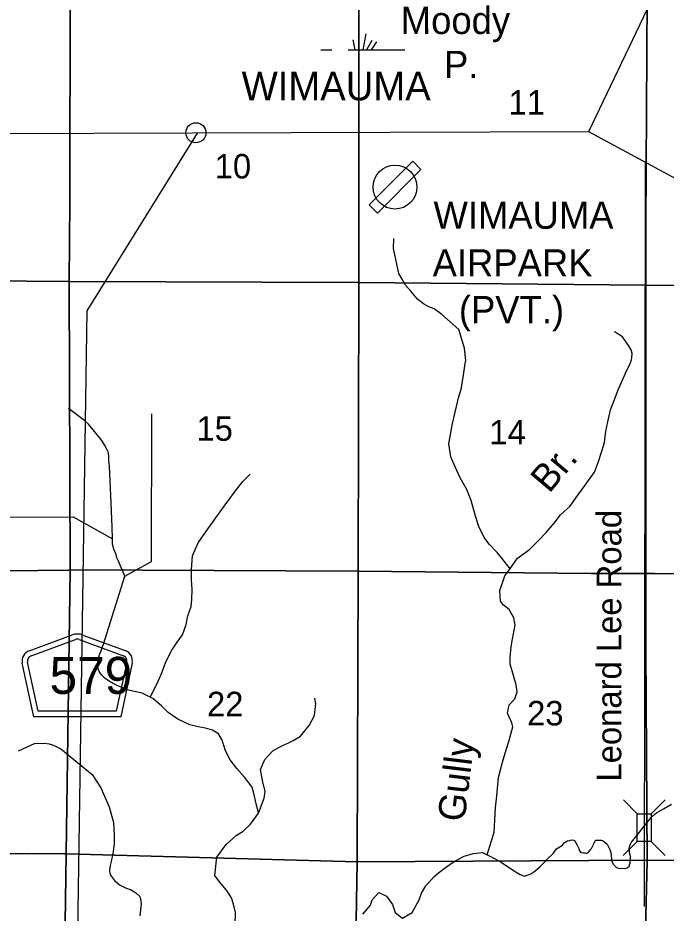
# Model space of a CAD drawing. Extents: x 380424 to 701066, y 1117407 to 1412949.
# Drawn here: x 557408 to 569307, y 1214030 to 1230461 of the extents above; entities that cross this region are included whole.
import ezdxf

# ---------------------------------------------------------------- set-up
doc = ezdxf.new("R2010")
doc.units = 0
for name, color, linetype in [('Airport Names', 7, 'Continuous'), ('Airports Landing Strip or Private Airport', 7, 'Continuous'), ('Bridges', 7, 'Continuous'), ('Bridges and Drawbridges Local Roads', 7, 'Continuous'), ('Communities Names with Post Office', 7, 'Continuous'), ('County Routes Highway Center Lines', 7, 'Continuous'), ('Local Roads Paved', 7, 'Continuous'), ('Local Roads Related Text', 7, 'Continuous'), ('Narrow Canals', 7, 'Continuous'), ('Narrow River Creek and Branch and Slough', 7, 'Continuous'), ('Narrow River Creek and Branch and Slough Text', 7, 'Continuous'), ('Roadshields County Roads', 7, 'Continuous'), ('Section Lines', 7, 'Continuous'), ('Section Numbers', 7, 'Continuous'), ('State Routes Highway Center Lines', 7, 'Continuous'), ('Swamps', 7, 'Continuous'), ('Town Centers', 7, 'Continuous')]:
    doc.layers.add(name, color=color, linetype=linetype)

msp = doc.modelspace()

# ---------------------------------------------------------------- linework, layer by layer
at = {"layer": 'Airports Landing Strip or Private Airport'}
msp.add_lwpolyline([(564655, 1227830), (563855, 1227030), (564006, 1226878), (564805, 1227680)], close=True, dxfattribs=at)
msp.add_circle((564330, 1227355), 403, dxfattribs=at)
at = {"layer": 'Bridges'}
msp.add_line((569033, 1215853), (569290, 1216109), dxfattribs=at)
at = {"layer": 'Bridges and Drawbridges Local Roads'}
for p, q in [((568777, 1215854), (568522, 1216110)), ((568776, 1215342), (568520, 1215086)), ((569032, 1215341), (569288, 1215085))]:
    msp.add_line(p, q, dxfattribs=at)
msp.add_lwpolyline([(569033, 1215853), (569032, 1215341), (568776, 1215342), (568777, 1215854)], close=True, dxfattribs=at)
at = {"layer": 'County Routes Highway Center Lines'}
msp.add_lwpolyline([(560790, 1209969), (558465, 1210808), (558680, 1225086), (560702, 1228346)], dxfattribs=at)
at = {"layer": 'Local Roads Paved'}
msp.add_line((568922, 1227813), (568903, 1214152), dxfattribs=at)
msp.add_lwpolyline([(571715, 1245267), (571679, 1236552), (571592, 1236125), (567880, 1228370)], dxfattribs=at)
at = {"layer": 'Narrow Canals'}
for points in [[(559858, 1220507), (559864, 1223191)], [(554061, 1221292), (558421, 1221302), (559147, 1220898)]]:
    msp.add_lwpolyline(points, dxfattribs=at)
at = {"layer": 'Narrow River Creek and Branch and Slough'}
for points in [[(566444, 1220351), (566292, 1220546), (566208, 1220646), (566067, 1220798), (565967, 1220924), (565867, 1221124), (565809, 1221313), (565731, 1221601), (565647, 1221806), (565526, 1222016), (565432, 1222220), (565353, 1222404), (565321, 1222640), (565384, 1223018), (565458, 1223328), (565495, 1223485), (565542, 1223648), (565584, 1223863), (565620, 1224115), (565631, 1224173), (565605, 1224398), (565500, 1224739), (565190, 1225017), (565048, 1225122), (564954, 1225159), (564854, 1225212), (564744, 1225296), (564618, 1225448), (564524, 1225558), (564461, 1225663), (564403, 1225768), (564303, 1226230), (564309, 1226413)], [(566025, 1215097), (566153, 1215518), (566164, 1215738), (566174, 1215959), (566200, 1216179), (566232, 1216520), (566305, 1216798), (566374, 1217029), (566421, 1217182), (566494, 1217449), (566473, 1217523), (566395, 1217701), (566426, 1217853), (566531, 1217963), (566573, 1218089), (566552, 1218221), (566494, 1218436), (566447, 1218598), (566447, 1218719), (566463, 1218919), (566489, 1219066), (566536, 1219312), (566510, 1219449), (566426, 1219601), (566321, 1219680), (566269, 1219753), (566253, 1219952), (566347, 1220220), (566437, 1220341), (566578, 1220545), (566799, 1220703), (566956, 1220860), (567103, 1221018), (567250, 1221186), (567371, 1221338), (567544, 1221501), (567654, 1221658), (567822, 1221884), (567995, 1222120), (568069, 1222319), (568121, 1222492), (568174, 1222666), (568200, 1222875), (568237, 1223049), (568289, 1223264), (568361, 1223459), (568425, 1223637), (568584, 1223993), (568642, 1224099), (568673, 1224183), (568678, 1224219), (568684, 1224303), (568663, 1224366), (568626, 1224430), (568573, 1224508), (568505, 1224608), (568374, 1224692), (568360, 1224700)], [(559370, 1220216), (559257, 1220489), (559226, 1220552), (559210, 1220610), (559168, 1220710), (559147, 1220804), (559147, 1220898), (559137, 1221119), (559121, 1221554), (559089, 1222231), (559079, 1222336), (559079, 1222420), (559063, 1222499), (559042, 1222546), (558995, 1222625), (558958, 1222688), (558932, 1222730), (558701, 1223003), (558638, 1223065), (558334, 1223291)], [(559834, 1217994), (559969, 1218258), (560063, 1218468), (560121, 1218641), (560236, 1218857), (560331, 1219003), (560430, 1219140), (560499, 1219324), (560530, 1219486), (560588, 1219659), (560598, 1219785), (560609, 1219969), (560593, 1220147), (560593, 1220336), (560614, 1220588), (560719, 1220824), (560903, 1221087), (561013, 1221239), (561212, 1221522), (561422, 1221806), (561538, 1221953), (561674, 1222089)], [(558982, 1218965), (559370, 1220216), (559858, 1220483), (559858, 1220507)], [(561827, 1215867), (561784, 1216038), (561753, 1216175), (561706, 1216338), (561569, 1216527), (561428, 1216684), (561302, 1216841), (561218, 1217009), (561160, 1217203), (561092, 1217319), (560981, 1217387), (560850, 1217424), (560714, 1217450), (560562, 1217487), (560462, 1217534), (560341, 1217587), (560168, 1217712), (560042, 1217833), (559885, 1217970), (559690, 1218064), (559406, 1218128)], [(561396, 1213803), (561401, 1214039), (561365, 1214191), (561328, 1214312), (561239, 1214448), (561107, 1214601), (561023, 1214721), (561060, 1215057), (561233, 1215288), (561412, 1215456), (561543, 1215535), (561679, 1215661), (561826, 1215865), (561931, 1216138), (561947, 1216259), (561895, 1216464), (561863, 1216663), (561942, 1216847), (562089, 1217009), (562251, 1217099), (562362, 1217151), (562461, 1217198), (562593, 1217277), (562755, 1217471), (562850, 1217655), (562876, 1217875), (562860, 1217975)], [(557416, 1217010), (557715, 1217141), (557888, 1217147), (557982, 1217136), (558045, 1217115), (558124, 1217084), (558197, 1217042), (558540, 1216762), (558769, 1216575), (558932, 1216328), (559084, 1215977), (559163, 1215693), (559173, 1215462), (559173, 1215300), (559152, 1215121), (559121, 1214974), (559100, 1214901), (559089, 1214822), (559089, 1214801), (559095, 1214765), (559110, 1214723), (559179, 1214628), (559273, 1214549), (559394, 1214486), (559472, 1214460), (559572, 1214402), (559640, 1214340), (559661, 1214292), (559672, 1214198), (559661, 1214088), (559646, 1213977)], [(563740, 1214007), (563882, 1214175), (563913, 1214274), (564034, 1214405), (564176, 1214342), (564286, 1214185), (564333, 1214038), (564469, 1213938), (564643, 1214043), (564774, 1214274), (564816, 1214395), (564894, 1214531), (565047, 1214699), (565131, 1214768), (565257, 1214867), (565419, 1214977), (565603, 1215077), (565766, 1215124), (565934, 1215140), (566143, 1215040), (566280, 1214962), (566485, 1214825), (566626, 1214736), (566705, 1214710), (566826, 1214752), (566899, 1214799), (566994, 1214883), (567057, 1214946), (567125, 1215019), (567235, 1215124), (567298, 1215208), (567403, 1215277), (567436, 1215321), (567495, 1215354), (567538, 1215363), (567570, 1215373), (567611, 1215369), (567639, 1215348), (567665, 1215296), (567676, 1215275), (567702, 1215217), (567718, 1215175), (567739, 1215143), (567791, 1215133), (567818, 1215133), (567839, 1215128), (567849, 1215128), (567891, 1215154), (567902, 1215175), (567912, 1215185), (567928, 1215201), (567939, 1215217), (567986, 1215312), (568012, 1215369), (568112, 1215369), (568154, 1215354), (568227, 1215296), (568275, 1215196), (568296, 1215117), (568306, 1214991), (568343, 1214923), (568396, 1214865), (568443, 1214849), (568490, 1214854), (568548, 1214849), (568590, 1214860), (568632, 1214896), (568637, 1214923), (568648, 1214939), (568653, 1215070), (568648, 1215096), (568637, 1215133), (568632, 1215170), (568632, 1215191), (568627, 1215212), (568632, 1215248), (568653, 1215296), (568674, 1215333), (569035, 1215783), (569069, 1215821), (569132, 1215868), (569258, 1215942), (569405, 1216031)]]:
    msp.add_lwpolyline(points, dxfattribs=at)
msp.add_spline([(559406, 1218128), (558881, 1218518), (558982, 1218965)], degree=3, dxfattribs=at)
at = {"layer": 'Roadshields County Roads'}
for p, q in [((557614, 1218846), (558394, 1219133)), ((558601, 1219133), (559379, 1218847)), ((557649, 1218752), (558463, 1219051)), ((558532, 1219051), (559344, 1218753)), ((557698, 1217634), (557488, 1218617)), ((557779, 1217734), (557586, 1218638)), ((559407, 1218638), (559214, 1217734)), ((559505, 1218617), (559295, 1217634)), ((559295, 1217634), (557698, 1217634)), ((559214, 1217734), (557779, 1217734))]:
    msp.add_line(p, q, dxfattribs=at)
for centre, radius, start, end in [((558497, 1218851), 300, 69.8272, 110.1733), ((558497, 1218957), 100, 69.8273, 110.1733), ((557683, 1218658), 200, 110.1733, 192.1002), ((557683, 1218658), 100, 110.1733, 192.1002), ((559310, 1218659), 100, 347.9004, 69.8273), ((559310, 1218659), 200, 347.9004, 69.8273)]:
    msp.add_arc(centre, radius, start, end, dxfattribs=at)
at = {"layer": 'Section Lines'}
for points in [[(558367, 1230965), (558367, 1230951), (558363, 1227091), (558349, 1225624), (558344, 1225624), (552958, 1225666), (553000, 1227840), (552979, 1230957), (552981, 1230983)], [(563667, 1230930), (563664, 1225602), (558349, 1225624), (558363, 1227091), (558367, 1230951), (558367, 1230965), (558377, 1230965), (560206, 1230956)], [(568961, 1230879), (568961, 1230874), (568937, 1226654), (568937, 1225557), (568930, 1225557), (563664, 1225602), (563667, 1230930), (568956, 1230879)], [(574266, 1230835), (574259, 1229902), (574243, 1226792), (574233, 1225522), (572751, 1225542), (568937, 1225557), (568937, 1226654), (568961, 1230874), (568961, 1230879), (574251, 1230835)], [(558349, 1225624), (558349, 1225607), (558366, 1220328), (558341, 1220327), (556635, 1220308), (553045, 1220329), (552955, 1225541), (552958, 1225666), (558344, 1225624)], [(563664, 1225602), (563664, 1225598), (563654, 1220309), (563655, 1220305), (563645, 1220305), (558366, 1220328), (558349, 1225607), (558349, 1225624)], [(568937, 1225557), (568936, 1222834), (568936, 1220264), (568933, 1220264), (567931, 1220264), (563655, 1220305), (563654, 1220309), (563664, 1225598), (563664, 1225602), (568930, 1225557)], [(574233, 1225522), (574222, 1223917), (574209, 1220222), (569101, 1220261), (568936, 1220264), (568936, 1222834), (568937, 1225557), (572751, 1225542)], [(558366, 1220328), (558366, 1220320), (558291, 1215124), (558291, 1215115), (558262, 1215116), (557590, 1215121), (555323, 1215079), (554461, 1215054), (553069, 1215043), (553064, 1215043), (553062, 1217440), (553045, 1220323), (553045, 1220329), (556635, 1220308), (558341, 1220327)], [(563655, 1220305), (563635, 1214979), (563635, 1214970), (560524, 1215057), (558291, 1215115), (558291, 1215124), (558366, 1220320), (558366, 1220328), (563645, 1220305)], [(568936, 1220264), (568935, 1218875), (568959, 1215004), (568954, 1215004), (563637, 1214969), (563635, 1214970), (563635, 1214979), (563655, 1220305), (567931, 1220264), (568933, 1220264)], [(574209, 1220222), (574204, 1217583), (574191, 1215017), (574188, 1214865), (574090, 1214865), (573003, 1214937), (571287, 1214987), (568959, 1215004), (568935, 1218875), (568936, 1220264), (569101, 1220261)], [(558291, 1215115), (558214, 1209643), (558206, 1209643), (553129, 1209685), (553124, 1209685), (553136, 1210657), (553064, 1215036), (553064, 1215043), (553069, 1215043), (554461, 1215054), (555323, 1215079), (557590, 1215121), (558262, 1215116)], [(563635, 1214970), (563592, 1212437), (563511, 1209636), (558214, 1209643), (558291, 1215115), (560524, 1215057)], [(568959, 1215004), (568959, 1214986), (568921, 1213469), (568837, 1210391), (568791, 1209623), (565255, 1209626), (563511, 1209636), (563592, 1212437), (563635, 1214970), (563637, 1214969), (568954, 1215004)], [(574188, 1214865), (574164, 1213654), (574071, 1209603), (574071, 1209592), (568799, 1209623), (568791, 1209623), (568837, 1210391), (568921, 1213469), (568959, 1214986), (568959, 1215004), (571287, 1214987), (573003, 1214937), (574090, 1214865)]]:
    msp.add_lwpolyline(points, close=True, dxfattribs=at)
at = {"layer": 'State Routes Highway Center Lines'}
msp.add_lwpolyline([(640551, 1225621), (608969, 1225590), (572811, 1225715), (567889, 1228370), (547875, 1228304), (542500, 1228290), (542132, 1228289), (536228, 1228275), (533934, 1228260), (532069, 1228431), (531223, 1228480), (521382, 1228594), (519319, 1228617), (515590, 1228660)], dxfattribs=at)
at = {"layer": 'Swamps'}
for p, q in [((563663, 1230131), (563663, 1229872)), ((563796, 1230167), (563737, 1229872)), ((563554, 1230058), (563591, 1229872)), ((563904, 1230046), (563810, 1229872)), ((563989, 1230022), (563890, 1229873))]:
    msp.add_line(p, q, dxfattribs=at)
for points in [[(562970, 1229872), (563172, 1229872)], [(563472, 1229872), (564512, 1229872)]]:
    msp.add_lwpolyline(points, dxfattribs=at)
at = {"layer": 'Town Centers'}
msp.add_circle((560676, 1228353), 184, dxfattribs=at)

# ---------------------------------------------------------------- texts
at = {"layer": 'Airport Names'}
for s, p in [('WIMAUMA', (565037, 1226590)), ('AIRPARK', (565021, 1225715)), ('(PVT.)', (565503, 1224856))]:
    msp.add_text(s, height=500, rotation=0.0003, dxfattribs=at).set_placement(p)
at = {"layer": 'Communities Names with Post Office'}
msp.add_text('WIMAUMA', height=525, rotation=0.0003, dxfattribs=at).set_placement((561515, 1228947))
at = {"layer": 'Local Roads Related Text'}
msp.add_text('Leonard Lee Road', height=450, rotation=90, dxfattribs=at).set_placement((568484, 1216444))
at = {"layer": 'Narrow River Creek and Branch and Slough Text'}
for s, rotation, p in [('Moody', 0.0003, (564437, 1230165)), ('P.', 0.0003, (565230, 1229356)), ('Br.', 49.9236, (567160, 1221719)), ('Gully', 83.0888, (565607, 1215692))]:
    msp.add_text(s, height=500, rotation=rotation, dxfattribs=at).set_placement(p)
at = {"layer": 'Roadshields County Roads'}
msp.add_text('579', height=680, rotation=0.0003, dxfattribs=at).set_placement((557989, 1218053))
at = {"layer": 'Section Numbers'}
for s, p in [('11', (566414, 1228685)), ('10', (561020, 1227514)), ('15', (560685, 1222699)), ('14', (566062, 1222631)), ('22', (560879, 1217642)), ('23', (566755, 1217474))]:
    msp.add_text(s, height=450, rotation=0.0003, dxfattribs=at).set_placement(p)

doc.saveas('drawing.dxf')
